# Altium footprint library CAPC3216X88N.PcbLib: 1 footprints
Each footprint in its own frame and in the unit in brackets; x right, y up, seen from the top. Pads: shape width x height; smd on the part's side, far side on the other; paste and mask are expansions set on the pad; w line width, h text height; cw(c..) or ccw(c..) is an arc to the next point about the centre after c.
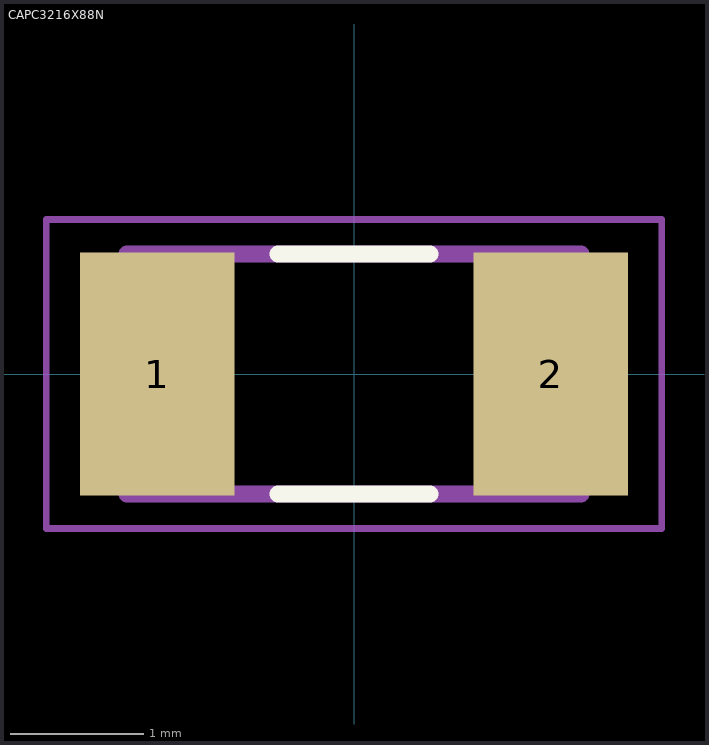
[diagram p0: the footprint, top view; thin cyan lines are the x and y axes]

## CAPC3216X88N [mm]
pads (2):
  rect 1.16x1.82 smd: 1(-1.475,0) 2(1.475,0)
Top Overlay:
  lines w0.127: -0.57,-0.9 0.57,-0.9 ; -0.57,0.9 0.57,0.9
Mechanical 13:
  lines w0.127: -1.7,-0.9 1.7,-0.9 1.7,0.9 -1.7,0.9 -1.7,-0.9
Mechanical 15:
  lines w0.05: -2.308,-1.158 2.308,-1.158 2.308,1.158 -2.308,1.158 -2.308,-1.158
